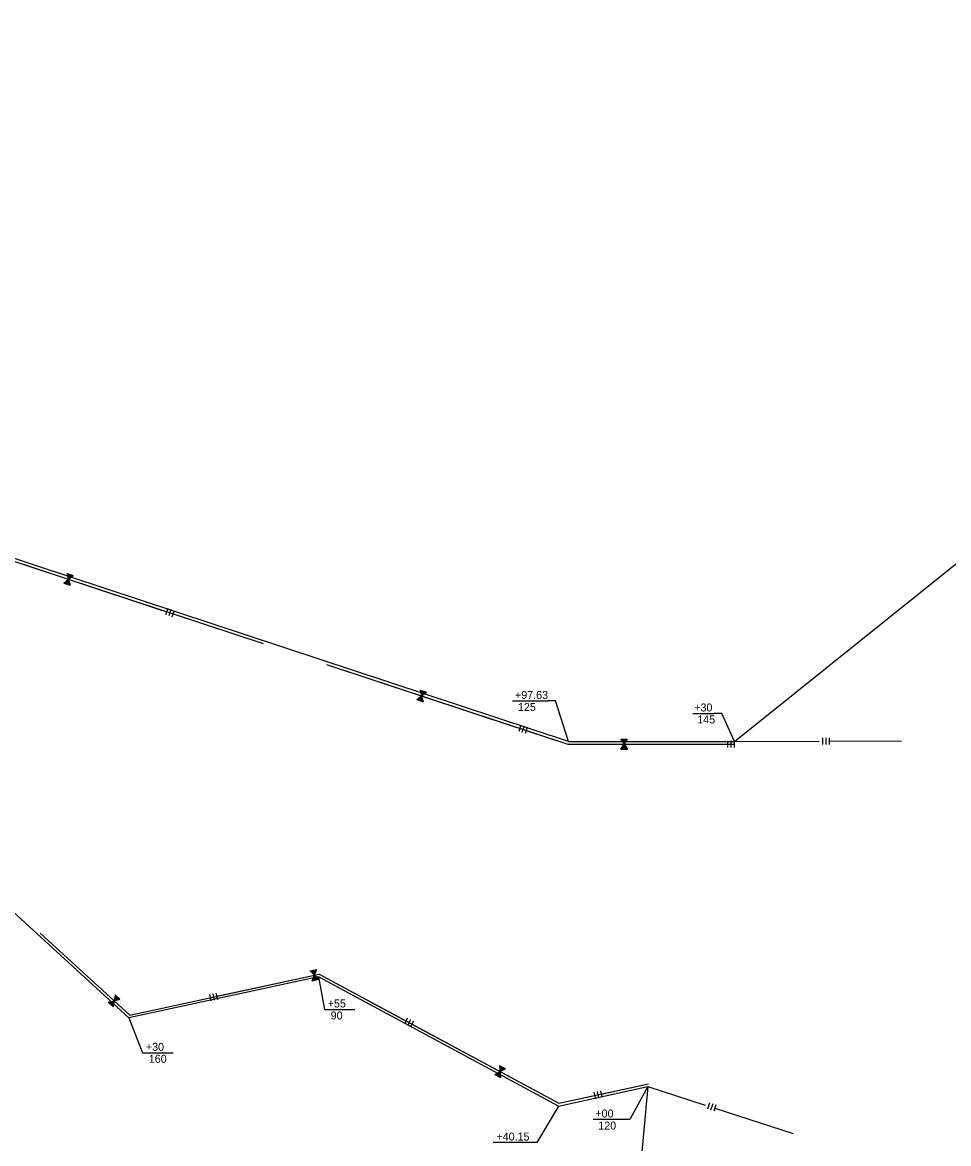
# Model space of a CAD drawing. Extents: x 979729 to 993523, y 1834148 to 1845433.
# Drawn here: x 983431 to 984124, y 1837582 to 1838423 of the extents above; entities that cross this region are included whole.
import ezdxf

# ---------------------------------------------------------------- set-up
doc = ezdxf.new("R2010")
doc.units = 0
for name, color, linetype in [('42', 7, 'Continuous'), ('51', 7, 'Continuous'), ('R_Draft', 7, 'Continuous')]:
    doc.layers.add(name, color=color, linetype=linetype)

msp = doc.modelspace()

# ---------------------------------------------------------------- linework, layer by layer
at = {"layer": '42'}
for p, q in [((982851.26, 1838208.07), (983611.03, 1837957.02)), ((983461.58, 1838002.45), (983465.13, 1838005.23)), ((983461.65, 1838002.49), (983461.67, 1838002.42)), ((983461.87, 1838002.63), (983461.95, 1838002.33)), ((983462.08, 1838002.82), (983462.24, 1838002.24)), ((983462.3, 1838002.97), (983462.53, 1838002.14)), ((983462.5, 1838003.15), (983462.81, 1838002.05)), ((983462.71, 1838003.34), (983463.1, 1838001.95)), ((983462.93, 1838003.49), (983463.38, 1838001.86)), ((983463.17, 1838003.57), (983463.62, 1838001.92)), ((983463.37, 1838003.79), (983463.95, 1838001.67)), ((983463.59, 1838003.94), (983464.24, 1838001.58)), ((983463.79, 1838004.15), (983464.52, 1838001.48)), ((983463.93, 1838009.57), (983465.13, 1838005.23)), ((983463.97, 1838009.51), (983464.02, 1838009.55)), ((983464.01, 1838004.27), (983464.81, 1838001.39)), ((983464.06, 1838009.26), (983464.31, 1838009.45)), ((983464.11, 1838008.98), (983464.59, 1838009.36)), ((983464.2, 1838008.73), (983464.88, 1838009.26)), ((983464.21, 1838004.49), (983465.09, 1838001.29)), ((983464.26, 1838008.46), (983465.16, 1838009.17)), ((983464.32, 1838008.19), (983465.45, 1838009.07)), ((983464.4, 1838007.94), (983465.73, 1838008.98)), ((983464.43, 1838004.63), (983465.38, 1838001.2)), ((983464.54, 1838007.73), (983465.89, 1838008.78)), ((983464.57, 1838007.43), (983466.3, 1838008.79)), ((983464.64, 1838004.82), (983465.66, 1838001.1)), ((983464.66, 1838007.19), (983466.59, 1838008.7)), ((983464.69, 1838006.9), (983466.87, 1838008.6)), ((983464.8, 1838006.66), (983467.16, 1838008.51)), ((983464.84, 1838006.37), (983467.45, 1838008.41)), ((983464.86, 1838004.94), (983465.95, 1838001.01)), ((983464.92, 1838006.13), (983467.73, 1838008.32)), ((983464.98, 1838005.85), (983468.02, 1838008.23)), ((983465.07, 1838005.15), (983466.23, 1838000.92)), ((983465.09, 1838005.62), (983468.3, 1838008.13)), ((983465.12, 1838005.33), (983468.59, 1838008.04)), ((983465.13, 1838005.23), (983468.68, 1838008.01)), ((983465.13, 1838005.23), (983466.33, 1838000.88)), ((983539.5, 1837983.29), (983537.93, 1837978.54)), ((983541.88, 1837982.5), (983540.31, 1837977.76)), ((983544.25, 1837981.72), (983542.68, 1837976.97)), ((983658.52, 1837941.33), (983839.3, 1837881.59)), ((983726.18, 1837915.02), (983729.73, 1837917.8)), ((983728.54, 1837922.14), (983729.73, 1837917.8)), ((983728.57, 1837922.07), (983728.62, 1837922.11)), ((983728.66, 1837921.82), (983728.91, 1837922.02)), ((983728.72, 1837921.55), (983729.2, 1837921.92)), ((983728.81, 1837921.3), (983729.48, 1837921.83)), ((983728.86, 1837921.03), (983729.77, 1837921.73)), ((983728.92, 1837920.75), (983730.05, 1837921.64)), ((983729.01, 1837920.51), (983730.34, 1837921.55)), ((983729.14, 1837920.3), (983730.49, 1837921.35)), ((983729.17, 1837920), (983730.91, 1837921.36)), ((983729.24, 1837917.39), (983730.27, 1837913.67)), ((983729.26, 1837919.75), (983731.19, 1837921.26)), ((983729.29, 1837919.46), (983731.48, 1837921.17)), ((983729.41, 1837919.23), (983731.76, 1837921.07)), ((983729.44, 1837918.94), (983732.05, 1837920.98)), ((983729.47, 1837917.51), (983730.55, 1837913.58)), ((983729.53, 1837918.69), (983732.33, 1837920.89)), ((983729.58, 1837918.42), (983732.62, 1837920.79)), ((983729.67, 1837917.72), (983730.84, 1837913.48)), ((983729.69, 1837918.19), (983732.9, 1837920.7)), ((983729.73, 1837917.9), (983733.19, 1837920.6)), ((983729.73, 1837917.8), (983733.28, 1837920.57)), ((983729.73, 1837917.8), (983730.93, 1837913.45)), ((983726.25, 1837915.05), (983726.27, 1837914.99)), ((983726.47, 1837915.2), (983726.56, 1837914.9)), ((983726.68, 1837915.39), (983726.84, 1837914.8)), ((983726.9, 1837915.53), (983727.13, 1837914.71)), ((983727.11, 1837915.72), (983727.41, 1837914.61)), ((983727.32, 1837915.9), (983727.7, 1837914.52)), ((983727.53, 1837916.05), (983727.98, 1837914.42)), ((983727.77, 1837916.14), (983728.22, 1837914.49)), ((983727.97, 1837916.36), (983728.55, 1837914.24)), ((983728.19, 1837916.51), (983728.84, 1837914.14)), ((983728.39, 1837916.72), (983729.12, 1837914.05)), ((983728.62, 1837916.84), (983729.41, 1837913.95)), ((983728.82, 1837917.05), (983729.7, 1837913.86)), ((983729.03, 1837917.2), (983729.98, 1837913.76)), ((983804.1, 1837895.85), (983802.54, 1837891.11)), ((983806.48, 1837895.07), (983804.91, 1837890.32)), ((983808.85, 1837894.28), (983807.28, 1837889.54)), ((983878.91, 1837885.35), (983881.41, 1837881.6)), ((983878.96, 1837885.3), (983879, 1837885.35)), ((983879.12, 1837885.09), (983879.3, 1837885.35)), ((983879.26, 1837884.84), (983879.6, 1837885.35)), ((983879.43, 1837884.64), (983879.9, 1837885.35)), ((983879.56, 1837884.39), (983880.2, 1837885.35)), ((983879.7, 1837884.15), (983880.5, 1837885.35)), ((983879.87, 1837883.94), (983880.8, 1837885.35)), ((983880.06, 1837883.79), (983881.01, 1837885.21)), ((983880.18, 1837883.52), (983881.4, 1837885.35)), ((983880.34, 1837883.31), (983881.7, 1837885.35)), ((983880.47, 1837883.04), (983882, 1837885.35)), ((983880.64, 1837882.86), (983882.3, 1837885.35)), ((983880.77, 1837882.59), (983882.6, 1837885.35)), ((983880.93, 1837882.39), (983882.9, 1837885.35)), ((983881.07, 1837882.14), (983883.2, 1837885.35)), ((983881.24, 1837881.96), (983883.51, 1837885.35)), ((983881.37, 1837881.69), (983883.81, 1837885.35)), ((983881.41, 1837881.6), (983883.91, 1837885.35)), ((983958.91, 1837884.12), (983958.91, 1837879.12)), ((983961.41, 1837884.12), (983961.41, 1837879.12)), ((983963.91, 1837884.12), (983963.91, 1837879.12)), ((984029.97, 1837886.42), (984029.99, 1837881.42)), ((984032.47, 1837886.43), (984032.49, 1837881.43)), ((984034.97, 1837886.44), (984034.99, 1837881.44)), ((983839.3, 1837881.59), (983963.97, 1837881.62)), ((983878.91, 1837877.85), (983881.41, 1837881.6)), ((983878.96, 1837877.9), (983879, 1837877.85)), ((983879.13, 1837878.11), (983879.3, 1837877.85)), ((983879.26, 1837878.35), (983879.6, 1837877.85)), ((983879.43, 1837878.56), (983879.9, 1837877.85)), ((983879.57, 1837878.81), (983880.2, 1837877.85)), ((983879.71, 1837879.05), (983880.5, 1837877.85)), ((983879.87, 1837879.26), (983880.8, 1837877.85)), ((983880.06, 1837879.41), (983881.01, 1837877.99)), ((983880.18, 1837879.68), (983881.4, 1837877.85)), ((983880.34, 1837879.89), (983881.71, 1837877.85)), ((983880.47, 1837880.16), (983882.01, 1837877.85)), ((983880.64, 1837880.34), (983882.31, 1837877.85)), ((983880.77, 1837880.61), (983882.61, 1837877.85)), ((983880.93, 1837880.82), (983882.91, 1837877.85)), ((983881.07, 1837881.06), (983883.21, 1837877.85)), ((983881.24, 1837881.24), (983883.51, 1837877.85)), ((983881.37, 1837881.51), (983883.81, 1837877.85)), ((983881.41, 1837881.6), (983883.91, 1837877.85)), ((983444.02, 1837739.96), (983511.06, 1837678.59)), ((983511.06, 1837678.59), (983652.87, 1837709.25)), ((983646.24, 1837711.65), (983649.47, 1837708.51)), ((983646.31, 1837711.61), (983646.33, 1837711.67)), ((983646.51, 1837711.44), (983646.62, 1837711.73)), ((983646.69, 1837711.23), (983646.92, 1837711.8)), ((983646.9, 1837711.06), (983647.21, 1837711.86)), ((983647.08, 1837710.86), (983647.5, 1837711.93)), ((983647.27, 1837710.65), (983647.8, 1837711.99)), ((983647.47, 1837710.48), (983648.09, 1837712.05)), ((983647.7, 1837710.37), (983648.32, 1837711.96)), ((983647.82, 1837704.32), (983649.47, 1837708.51)), ((983647.87, 1837710.13), (983648.68, 1837712.18)), ((983648.07, 1837709.96), (983648.97, 1837712.24)), ((983648.25, 1837709.73), (983649.27, 1837712.31)), ((983648.46, 1837709.58), (983649.56, 1837712.37)), ((983648.64, 1837709.35), (983649.85, 1837712.43)), ((983648.84, 1837709.18), (983650.15, 1837712.5)), ((983649, 1837707.12), (983651.15, 1837705.04)), ((983649.03, 1837708.97), (983650.44, 1837712.56)), ((983649.06, 1837707.41), (983651.44, 1837705.1)), ((983649.17, 1837707.65), (983651.73, 1837705.17)), ((983649.24, 1837708.83), (983650.73, 1837712.62)), ((983649.26, 1837707.91), (983652.02, 1837705.23)), ((983649.39, 1837708.13), (983652.32, 1837705.29)), ((983649.42, 1837708.6), (983651.03, 1837712.69)), ((983649.46, 1837708.42), (983652.61, 1837705.36)), ((983649.47, 1837708.51), (983651.13, 1837712.71)), ((983649.47, 1837708.51), (983652.71, 1837705.38)), ((983652.87, 1837709.25), (983832.44, 1837612.46)), ((983647.87, 1837704.39), (983647.91, 1837704.34)), ((983647.98, 1837704.62), (983648.21, 1837704.4)), ((983648.07, 1837704.89), (983648.5, 1837704.47)), ((983648.18, 1837705.13), (983648.8, 1837704.53)), ((983648.26, 1837705.39), (983649.09, 1837704.59)), ((983648.35, 1837705.66), (983649.38, 1837704.66)), ((983648.46, 1837705.9), (983649.68, 1837704.72)), ((983648.62, 1837706.09), (983649.85, 1837704.9)), ((983648.68, 1837706.38), (983650.26, 1837704.85)), ((983648.8, 1837706.62), (983650.56, 1837704.91)), ((983648.86, 1837706.91), (983650.85, 1837704.98)), ((983500.03, 1837693.77), (983499.34, 1837689.31)), ((983499.34, 1837689.31), (983503.72, 1837690.39)), ((983499.37, 1837689.41), (983503.64, 1837690.46)), ((983499.46, 1837689.94), (983503.2, 1837690.86)), ((983499.46, 1837689.69), (983503.42, 1837690.66)), ((983499.52, 1837690.21), (983502.98, 1837691.07)), ((983499.54, 1837690.48), (983502.76, 1837691.27)), ((983499.62, 1837691.01), (983502.31, 1837691.67)), ((983499.63, 1837690.76), (983502.54, 1837691.47)), ((983499.71, 1837691.29), (983502.09, 1837691.88)), ((983499.73, 1837691.55), (983501.87, 1837692.08)), ((983499.79, 1837692.08), (983501.43, 1837692.49)), ((983499.81, 1837692.35), (983501.21, 1837692.69)), ((983499.83, 1837691.84), (983501.49, 1837692.24)), ((983499.87, 1837692.62), (983500.98, 1837692.89)), ((983499.93, 1837692.89), (983500.76, 1837693.09)), ((983499.95, 1837693.15), (983500.54, 1837693.3)), ((983500.01, 1837693.43), (983500.32, 1837693.5)), ((983500.03, 1837693.69), (983500.1, 1837693.7)), ((983570.75, 1837694.05), (983571.81, 1837689.17)), ((983573.2, 1837694.58), (983574.25, 1837689.69)), ((983575.64, 1837695.11), (983576.7, 1837690.22)), ((983494.96, 1837688.23), (983499.34, 1837689.31)), ((983495.04, 1837688.24), (983495.03, 1837688.17)), ((983495.3, 1837688.28), (983495.25, 1837687.97)), ((983495.57, 1837688.37), (983495.48, 1837687.77)), ((983495.83, 1837688.41), (983495.7, 1837687.56)), ((983496.09, 1837688.5), (983495.92, 1837687.36)), ((983496.36, 1837688.58), (983496.14, 1837687.16)), ((983496.62, 1837688.62), (983496.36, 1837686.95)), ((983496.87, 1837688.6), (983496.61, 1837686.92)), ((983497.14, 1837688.73), (983496.81, 1837686.55)), ((983497.4, 1837688.77), (983497.03, 1837686.35)), ((983497.67, 1837688.88), (983497.25, 1837686.14)), ((983497.93, 1837688.9), (983497.47, 1837685.94)), ((983498.2, 1837689.01), (983497.69, 1837685.74)), ((983498.46, 1837689.06), (983497.91, 1837685.53)), ((983498.72, 1837689.14), (983498.13, 1837685.33)), ((983498.98, 1837689.16), (983498.36, 1837685.13)), ((983499.25, 1837689.27), (983498.58, 1837684.93)), ((983499.34, 1837689.31), (983498.65, 1837684.86)), ((983719.22, 1837676.33), (983716.85, 1837671.93)), ((983721.42, 1837675.14), (983719.05, 1837670.74)), ((983723.62, 1837673.95), (983721.25, 1837669.55)), ((983788.03, 1837640.66), (983788.45, 1837636.17)), ((983788.06, 1837640.58), (983788.11, 1837640.61)), ((983788.1, 1837640.32), (983788.38, 1837640.47)), ((983788.11, 1837640.04), (983788.64, 1837640.33)), ((983788.15, 1837639.78), (983788.91, 1837640.18)), ((983788.16, 1837639.5), (983789.17, 1837640.04)), ((983788.17, 1837639.22), (983789.44, 1837639.9)), ((983784.47, 1837634.05), (983788.45, 1837636.17)), ((983784.55, 1837634.07), (983784.56, 1837634.01)), ((983784.79, 1837634.18), (983784.82, 1837633.87)), ((983785.03, 1837634.33), (983785.08, 1837633.72)), ((983785.27, 1837634.43), (983785.35, 1837633.58)), ((983785.51, 1837634.58), (983785.61, 1837633.44)), ((983785.74, 1837634.73), (983785.88, 1837633.3)), ((983785.99, 1837634.84), (983786.14, 1837633.15)), ((983786.23, 1837634.88), (983786.39, 1837633.18)), ((983786.47, 1837635.06), (983786.67, 1837632.87)), ((983786.71, 1837635.17), (983786.94, 1837632.73)), ((983786.94, 1837635.34), (983787.2, 1837632.58)), ((983787.19, 1837635.42), (983787.47, 1837632.44)), ((983787.42, 1837635.6), (983787.73, 1837632.3)), ((983787.66, 1837635.7), (983787.99, 1837632.16)), ((983787.9, 1837635.85), (983788.26, 1837632.01)), ((983788.14, 1837635.93), (983788.52, 1837631.87)), ((983788.21, 1837638.96), (983789.7, 1837639.76)), ((983788.29, 1837638.44), (983790.23, 1837639.47)), ((983788.31, 1837638.73), (983789.82, 1837639.54)), ((983788.31, 1837637.89), (983790.76, 1837639.19)), ((983788.33, 1837638.18), (983790.5, 1837639.33)), ((983788.36, 1837637.35), (983791.29, 1837638.9)), ((983788.38, 1837637.64), (983791.02, 1837639.04)), ((983788.38, 1837636.11), (983788.79, 1837631.73)), ((983788.41, 1837637.09), (983791.55, 1837638.76)), ((983788.41, 1837636.81), (983791.82, 1837638.62)), ((983788.45, 1837636.17), (983792.43, 1837638.28)), ((983788.45, 1837636.17), (983788.88, 1837631.68)), ((983788.46, 1837636.27), (983792.35, 1837638.33)), ((983788.48, 1837636.56), (983792.08, 1837638.47)), ((983832.44, 1837612.46), (983899.58, 1837627.1)), ((983858.81, 1837620.77), (983859.87, 1837615.88)), ((983861.25, 1837621.3), (983862.31, 1837616.42)), ((983863.69, 1837621.83), (983864.76, 1837616.95)), ((983945.39, 1837612.76), (983943.85, 1837608)), ((983947.77, 1837611.99), (983946.23, 1837607.23)), ((983950.15, 1837611.22), (983948.61, 1837606.46))]:
    msp.add_line(p, q, dxfattribs=at)
for points in [[(983393.92, 1838028.76), (983536.34, 1837981.7)], [(983461.58, 1838002.45), (983466.33, 1838000.88)], [(983463.93, 1838009.57), (983468.68, 1838008.01)], [(983543.46, 1837979.34), (983611.03, 1837957.02)], [(983658.52, 1837941.33), (983800.95, 1837894.26)], [(983728.54, 1837922.14), (983733.28, 1837920.57)], [(983726.18, 1837915.02), (983730.93, 1837913.45)], [(983808.07, 1837891.91), (983839.3, 1837881.59), (983956.41, 1837881.62)], [(983878.91, 1837885.35), (983883.91, 1837885.35)], [(983964.23, 1837883.62), (984027.48, 1837883.91)], [(984034.98, 1837883.94), (984089.1, 1837884.19)], [(983878.91, 1837877.85), (983883.91, 1837877.85)], [(983963.91, 1837881.62), (983963.97, 1837881.62)], [(983444.02, 1837739.96), (983511.06, 1837678.59), (983568.84, 1837691.08)], [(983576.17, 1837692.67), (983652.87, 1837709.25), (983715.83, 1837675.31)], [(983646.24, 1837711.65), (983651.13, 1837712.71)], [(983647.82, 1837704.32), (983652.71, 1837705.38)], [(983500.03, 1837693.77), (983503.72, 1837690.39)], [(983494.96, 1837688.23), (983498.65, 1837684.86)], [(983722.43, 1837671.75), (983832.44, 1837612.46), (983856.9, 1837617.79)], [(983788.03, 1837640.66), (983792.43, 1837638.28)], [(983784.47, 1837634.05), (983788.88, 1837631.68)], [(983864.22, 1837619.39), (983899.58, 1837627.1)], [(983899.28, 1837624.99), (983942.24, 1837611.14)], [(983949.38, 1837608.84), (984008.18, 1837589.89)]]:
    msp.add_lwpolyline(points, dxfattribs=at)
at = {"layer": '51'}
for points in [[(983839.63, 1837883.59), (982851.76, 1838210.02), (982490.82, 1838277.42), (982183.3, 1838422.69)], [(983839.63, 1837883.59), (983964.23, 1837883.62), (984287.23, 1838143), (984453.05, 1838392.87), (984546.56, 1838335.6), (984387.83, 1838097.74), (984180.84, 1837884.6), (984295.61, 1837882.99), (984364.62, 1837995.97), (984581.88, 1838016.14), (985008.02, 1838103.48), (985091.14, 1838121.27)], [(983832.14, 1837610.35), (983652.57, 1837707.14), (983510.47, 1837676.41), (983408.2, 1837770.04), (983207.39, 1837710.64), (983118.6, 1837831.53), (982865.15, 1837788.06), (982600.28, 1837983.11), (982196.59, 1837995.54), (982113.58, 1838135.58), (981690.98, 1838258.2), (981584.78, 1838227.65)], [(983832.14, 1837610.35), (983899.28, 1837624.99), (983877.1, 1837385.75), (983914.53, 1837124.26), (983905.65, 1836909.01), (984013.18, 1836905.08), (984017.58, 1837080.16), (984054.32, 1837258.25), (984179.74, 1837534.6), (984311.6, 1837538.33), (984765.43, 1837671.12), (985159.91, 1837767.88)]]:
    msp.add_lwpolyline(points, dxfattribs=at)
at = {"layer": 'R_Draft'}
for p, q in [((983797.89, 1837914.04), (983823.93, 1837914.04)), ((983932.88, 1837904.67), (983948.68, 1837904.67)), ((983663, 1837682.79), (983679.76, 1837682.79)), ((983526.72, 1837650.3), (983543.49, 1837650.3)), ((983879.7, 1837600.38), (983858.12, 1837600.38)), ((983809.94, 1837583.01), (983783.35, 1837583.01))]:
    msp.add_line(p, q, dxfattribs=at)
for points in [[(983839.63, 1837883.59), (983829.93, 1837914.04), (983823.93, 1837914.04)], [(983964.23, 1837883.62), (983954.68, 1837904.67), (983948.68, 1837904.67)], [(983652.57, 1837707.14), (983657, 1837682.79), (983663, 1837682.79)], [(983510.47, 1837676.41), (983520.72, 1837650.3), (983526.72, 1837650.3)], [(983899.28, 1837624.99), (983885.7, 1837600.38), (983879.7, 1837600.38)], [(983832.14, 1837610.35), (983815.94, 1837583.01), (983809.94, 1837583.01)]]:
    msp.add_lwpolyline(points, dxfattribs=at)

# ---------------------------------------------------------------- texts
for s, p in [('+97.63', (983799.66, 1837915.54)), (' 125', (983799.66, 1837906.54)), ('+30', (983933.96, 1837906.17)), (' 145', (983933.96, 1837897.17)), ('+55', (983659.38, 1837684.29)), (' 90', (983659.38, 1837675.29)), ('+30', (983523.1, 1837651.8)), (' 160', (983523.1, 1837642.8)), ('+00', (983859.85, 1837601.79)), (' 120', (983859.85, 1837592.79)), ('+40.15', (983785.77, 1837584.51))]:
    msp.add_text(s, height=6, rotation=360, dxfattribs=at).set_placement(p)

doc.saveas('drawing.dxf')
